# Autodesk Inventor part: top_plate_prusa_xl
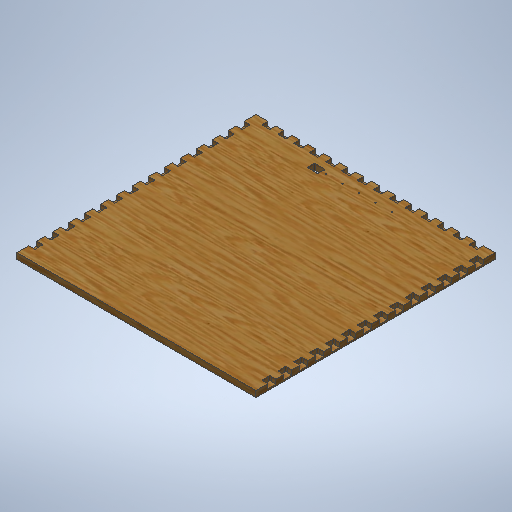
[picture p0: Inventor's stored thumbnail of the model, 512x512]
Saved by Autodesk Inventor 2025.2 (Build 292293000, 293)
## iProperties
Created: 2024-11
Part Number: top_plate_prusa_xl
Material: Plywood, Finish
Document SubType Name: Modeling
Designer: BennF
Density: 0.552 g/cm^3
Appearance: Plywood - New
Author: BennF
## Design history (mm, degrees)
sketch "Sketch2"
  geometry: L1 (-360, 360)-(360, 360); L2 (360, 360)-(360, -360); L3 (360, -360)-(-360, -360); L4 (-360, -360)-(-360, 360); 3 further points
  constraints: 8 end point, 2 midpoint, 2 parallel, 1 horizontal, 1 horizontal alignment, 1 perpendicular, 1 vertical alignment
  dimensions: "d0" = 720 distance of L1.start L1.end (= prusa_xl_width); "d1" = 720 distance of L3.end L1.start (= prusa_xl_depth)
extrude "base_material" new body sketch "Sketch2" distance "d2" = 18 (= thickness); taper "d3" = 0 deg
sketch "Sketch3"
  geometry: L1 (-324, 360)-(-324, 341.8); L2 (-324, 341.8)-(-300, 341.8); L3 (-300, 341.8)-(-300, 360); L4 (-276, 360)-(-276, 341.8); L5 (-276, 341.8)-(-252, 341.8); L6 (-252, 341.8)-(-252, 360); L7 (-228, 360)-(-228, 341.8); L8 (-228, 341.8)-(-204, 341.8); L9 (-204, 341.8)-(-204, 360); L10 (-180, 360)-(-180, 341.8); L11 (-180, 341.8)-(-156, 341.8); L12 (-156, 341.8)-(-156, 360); L13 (-132, 360)-(-132, 341.8); L14 (-132, 341.8)-(-108, 341.8); L15 (-108, 341.8)-(-108, 360); L16 (-84, 360)-(-84, 341.8); L17 (-84, 341.8)-(-60, 341.8); L18 (-60, 341.8)-(-60, 360); L19 (-36, 360)-(-36, 341.8); L20 (-36, 341.8)-(-12, 341.8); L21 (-12, 341.8)-(-12, 360); L22 (12, 360)-(12, 341.8); L23 (12, 341.8)-(36, 341.8); L24 (36, 341.8)-(36, 360); L25 (60, 360)-(60, 341.8); L26 (60, 341.8)-(84, 341.8); L27 (84, 341.8)-(84, 360); L28 (108, 360)-(108, 341.8); L29 (108, 341.8)-(132, 341.8); L30 (132, 341.8)-(132, 360); L31 (156, 360)-(156, 341.8); L32 (156, 341.8)-(180, 341.8); L33 (180, 341.8)-(180, 360); L34 (204, 360)-(204, 341.8); L35 (204, 341.8)-(228, 341.8); L36 (228, 341.8)-(228, 360); L37 (252, 360)-(252, 341.8); L38 (252, 341.8)-(276, 341.8); L39 (276, 341.8)-(276, 360); L40 (300, 360)-(300, 341.8); L41 (300, 341.8)-(324, 341.8); L42 (324, 341.8)-(324, 360); L43 (-360, -324)-(-341.8, -324); L44 (-341.8, -324)-(-341.8, -300); L45 (-341.8, -300)-(-360, -300); L46 (-341.8, -252)-(-360, -252); L47 (-341.8, -276)-(-341.8, -252); L48 (-360, -276)-(-341.8, -276); L49 (-341.8, -204)-(-360, -204); L50 (-341.8, -228)-(-341.8, -204); L51 (-360, -228)-(-341.8, -228); L52 (-341.8, -156)-(-360, -156); L53 (-341.8, -180)-(-341.8, -156); L54 (-360, -180)-(-341.8, -180); L55 (-341.8, -108)-(-360, -108); L56 (-341.8, -132)-(-341.8, -108); L57 (-360, -132)-(-341.8, -132); L58 (-341.8, -60)-(-360, -60); L59 (-341.8, -84)-(-341.8, -60); L60 (-360, -84)-(-341.8, -84); L61 (-341.8, -12)-(-360, -12); L62 (-341.8, -36)-(-341.8, -12); L63 (-360, -36)-(-341.8, -36); L64 (-341.8, 36)-(-360, 36)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; 81 further points
  constraints: 252 end point, 104 vertical alignment, 78 parallel, 53 horizontal alignment, 39 collinear, 6 perpendicular, 2 equal length, 2 horizontal, 1 vertical, 9 other
  dimensions: "d4" = 24 distance of L1.end L2.end (= finger_width); "d5" = 18.2 distance of L2.end L3.end (derived); "d8" = 48 distance of L1.start L4.start (= finger_distance); "d13" = 24 distance of L43.end L44.end (= finger_width); "d14" = 18.2 distance of L44.end L45.end (derived); "d17" = 48 distance of L45.end L46.end (= finger_distance); "d48" = 36 distance between parallel lines of L85 L43 (derived); "d49" = 36 dimension on L1 (derived); "d52" = 48 distance of L86.start L89.start (derived)
extrude "joints" cut sketch "Sketch3" distance "d22" = 13.5 (derived); taper "d23" = 0 deg
sketch "Sketch4" dims "d24" = 6 (= dogbone_diameter)
  geometry: L1 (-341.8, -228)-(-360, -228) reference; L2 (-360, -228)-(-360, -252) reference; L3 (-360, -252)-(-341.8, -252) reference; L4 (-341.8, -252)-(-341.8, -276) reference; L5 (-341.8, -276)-(-360, -276) reference; L6 (-360, -276)-(-360, -300) reference; L7 (-360, -300)-(-341.8, -300) reference; L8 (-341.8, -300)-(-341.8, -324) reference; L9 (-341.8, -324)-(-360, -324) reference; L10 (-360, -324)-(-360, -360) reference; L11 (-360, -360)-(360, -360) reference; L12 (360, -360)-(360, -324) reference; L13 (360, 360)-(324, 360) reference; L14 (132, 360)-(132, 341.8) reference; L15 (132, 341.8)-(108, 341.8) reference; L16 (108, 341.8)-(108, 360) reference; L17 (108, 360)-(84, 360) reference; L18 (84, 360)-(84, 341.8) reference; L19 (84, 341.8)-(60, 341.8) reference; L20 (60, 341.8)-(60, 360) reference; L21 (60, 360)-(36, 360) reference; L22 (36, 360)-(36, 341.8) reference; L23 (36, 341.8)-(12, 341.8) reference; L24 (12, 341.8)-(12, 360) reference; L25 (12, 360)-(-12, 360) reference; L26 (-12, 360)-(-12, 341.8) reference; L27 (-12, 341.8)-(-36, 341.8) reference; L28 (-36, 341.8)-(-36, 360) reference; L29 (-36, 360)-(-60, 360) reference; L30 (-60, 360)-(-60, 341.8) reference; L31 (-60, 341.8)-(-84, 341.8) reference; L32 (-84, 341.8)-(-84, 360) reference; L33 (-84, 360)-(-108, 360) reference; L34 (-108, 360)-(-108, 341.8) reference; L35 (-108, 341.8)-(-132, 341.8) reference; L36 (-132, 341.8)-(-132, 360) reference; L37 (-132, 360)-(-156, 360) reference; L38 (-156, 360)-(-156, 341.8) reference; L39 (-156, 341.8)-(-180, 341.8) reference; L40 (-180, 341.8)-(-180, 360) reference; L41 (-180, 360)-(-204, 360) reference; L42 (-204, 360)-(-204, 341.8) reference; L43 (-204, 341.8)-(-228, 341.8) reference; L44 (-228, 341.8)-(-228, 360) reference; L45 (-228, 360)-(-252, 360) reference; L46 (-252, 360)-(-252, 341.8) reference; L47 (-252, 341.8)-(-276, 341.8) reference; L48 (-276, 341.8)-(-276, 360) reference; L49 (-276, 360)-(-300, 360) reference; L50 (-300, 360)-(-300, 341.8) reference; L51 (-300, 341.8)-(-324, 341.8) reference; L52 (-324, 341.8)-(-324, 360) reference; L53 (-324, 360)-(-360, 360) reference; L54 (-360, 360)-(-360, 324) reference; L55 (-360, 324)-(-341.8, 324) reference; L56 (-341.8, 324)-(-341.8, 300) reference; L57 (-341.8, 300)-(-360, 300) reference; L58 (-360, 300)-(-360, 276) reference; L59 (-360, 276)-(-341.8, 276) reference; L60 (-341.8, 276)-(-341.8, 252) reference; L61 (-341.8, 252)-(-360, 252) reference; L62 (-360, 252)-(-360, 228) reference; L63 (-360, 228)-(-341.8, 228) reference; L64 (-341.8, 228)-(-341.8, 204) reference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; 153 further points
  constraints: 118 end point, 58 point on line, 54 vertical, 27 horizontal, 5 midpoint, 3 perpendicular, 2 horizontal alignment, 1 vertical alignment, 525 other
  dimensions: "d27" = 48 distance of L7.end L104.start (= finger_distance); "d34" = 48 distance of L50.end L133.end (= finger_distance); "d70" = 48 distance of L159.end point (341.8, -276) (derived)
extrude "dogbones" cut sketch "Sketch4" distance "d39" = 13.5 (derived); taper "d40" = 0 deg
sketch "Sketch5"
  geometry: L1 (-142, 321)-(-116, 321); L2 (-113, 318)-(-113, 302); L3 (-116, 299)-(-142, 299); L4 (-145, 302)-(-145, 318); L5 (-360, 360)-(-360, 324) reference; L6 (-324, 360)-(-360, 360) reference; L7 (-250, 310)-(250, 310); A1 r 3 centre (-142, 318) between (-142, 321) and (-145, 318); A2 r 3 centre (-142, 302) between (-145, 302) and (-142, 299); A3 r 3 centre (-116, 302) between (-116, 299) and (-113, 302); A4 r 3 centre (-116, 318) between (-113, 318) and (-116, 321); 10 further points
  constraints: 10 end point, 8 point on circle, 8 point on line, 8 tangent, 4 centre point, 4 midpoint, 3 equal radius, 2 horizontal, 2 parallel, 1 coincident, 1 horizontal alignment, 1 perpendicular, 1 vertical alignment
  dimensions: "d57" = 32 distance of point (-145, 321) point (-113, 321) (derived); "d58" = 22 distance of point (-145, 299) point (-145, 321) (derived); "d60" = 50 distance from line of point (-145, 310) L6 (derived); "d65" = 3 radius of A1 (derived); "d66" = 500 distance of L7.start L7.end (derived); "d67" = 105 distance from line of L7.start L4 (derived)
extrude "cable_hole" cut sketch "Sketch5" distance "d63" = 18 (derived); taper "d64" = 0 deg
sketch "Sketch6"
  geometry: L1 (-113, 318)-(-113, 302) reference; L2 (-100, 310)-(-50, 310); L3 (-50, 310)-(0, 310); L4 (0, 310)-(50, 310); L5 (50, 310)-(100, 310); 2 further points
  constraints: 8 end point, 6 collinear, 5 horizontal alignment, 1 horizontal, 1 midpoint, 1 vertical alignment
  dimensions: "d82" = 50 distance of L2.start L2.end (derived)
hole "Hole1" sketch "Sketch6" at (-100, 310), (-50, 310), (0, 310), (50, 310), (100, 310) diameter "d75" = 4 (derived); stored, may be unused: countersink angle "d79" = 90 deg, drill point angle "d81" = 118 deg; dims "d76" = 6, "d77" = 7.5, "d78" = 2, "d80" = 8
body "Solid1"
node "Sketch Rectangular Pattern1" dims "d8" = 48 (= finger_distance), "d11" = 10
node "Sketch Rectangular Pattern2" dims "d17" = 48 (= finger_distance), "d20" = 10
node "Projected Loop1"
node "Sketch Rectangular Pattern3" dims "d27" = 48 (= finger_distance), "d30" = 10
node "Sketch Rectangular Pattern4" dims "d34" = 48 (= finger_distance), "d37" = 10
node "Sketch Rectangular Pattern6" dims "d52" = 48 (derived), "d55" = 10
node "Sketch Rectangular Pattern7" dims "d70" = 48 (derived), "d73" = 10
other parameters: "thickness" = 18 [user parameter; used in 1 equation term], "prusa_xl_depth" = 720 [user parameter; used in 1 equation term], "finger_depth" = 18 [user parameter], "prusa_xl_width" = 720 [user parameter; used in 1 equation term], "finger_width" = 24 [user parameter; used in 2 equation terms], "dogbone_diameter" = 6 [user parameter; used in 1 equation term], "finger_distance" = 48 [user parameter; used in 4 equation terms], "mill_bit" = 6 [user parameter], "dogbone_angle" = 45 deg [user parameter], "prusa_xl_depth_finger_distance" = 36 [user parameter], "prusa_xl_height" = 1005 [user parameter], "prusa_xl_height_finger_distance" = 34.5 [user parameter], "prusa_xl_width_finger_distance" = 36 [user parameter], "prusa_xl_shelf_depth" = 702 [user parameter], "prusa_xl_shelf_width" = 684 [user parameter], "box_clearence_1" = 9.33333 [user parameter], "box_height_1" = 435 [user parameter], "box_height_2" = 235 [user parameter], "hidden_depth" = 4.5 [user parameter], "connection_clearence" = 0.2 [user parameter], "sla_width" = 1296 [user parameter], "back_distance" = 5 [user parameter], "back_connection_depth" = 5 [user parameter], "storage_width_2" = 322 [user parameter], "box_clearence_2" = 24.33333 [user parameter], "shelf_depth_finger_distance" = 39 [user parameter], "connection_back_clearence" = 0 [user parameter], "thickness_back" = 6 [user parameter], "finger_depth_middle" = 8 [user parameter], "box_height_3" = 285 [user parameter], "bowden_tube_diameter" = 4 [user parameter], "connector_width_offset" = 105 [user parameter], "connector_width" = 26 [user parameter], "connector_depth" = 16 [user parameter]
